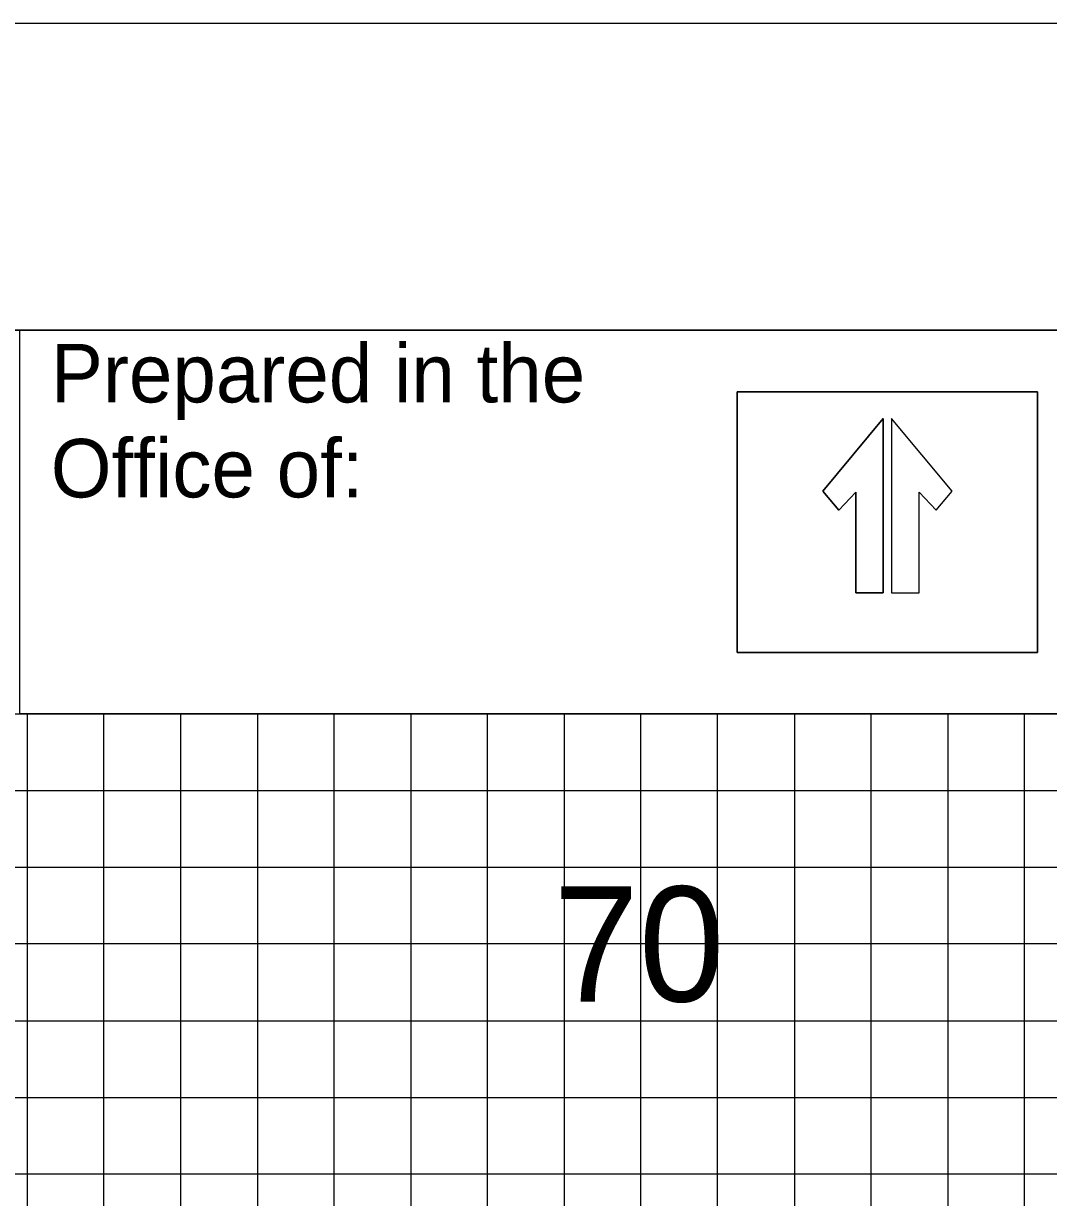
# Model space of a CAD drawing. Extents: x -13 to 323, y 655 to 874.
# Drawn here: x 221.95 to 235.31, y 858.69 to 874 of the extents above; entities that cross this region are included whole.
import ezdxf

# ---------------------------------------------------------------- set-up
doc = ezdxf.new("R2010")
doc.units = 0
for name, color, linetype in [('Exist Cross Section Cell', 7, 'Continuous'), ('Prop CMT Guardrail Widen Shoulder', 7, 'Continuous'), ('Prop CMT Pvmt Course 3', 7, 'Continuous'), ('Prop CMT Shld Paved Course 1', 7, 'Continuous'), ('Prop CMT Shld Paved Course 2', 7, 'Continuous'), ('Prop CMT Shld Paved Course 3', 7, 'Continuous'), ('Prop CMT Slope Grass', 7, 'Continuous'), ('Prop CMT Subgrade Earthwork', 7, 'Continuous'), ('Prop XS Earthwork Shape', 7, 'Continuous'), ('Scratch_Level_3', 7, 'Continuous')]:
    doc.layers.add(name, color=color, linetype=linetype)

msp = doc.modelspace()

# ---------------------------------------------------------------- linework, layer by layer
at = {"layer": 'Prop CMT Guardrail Widen Shoulder'}
for points in [[(235.168, 869.199), (231.253, 869.199), (231.253, 865.801), (235.168, 865.801), (235.168, 869.199)], [(233.158, 868.851), (233.158, 866.579), (232.8, 866.579), (232.8, 867.89), (232.578, 867.655), (232.37, 867.904), (233.158, 868.851)], [(232.37, 867.904), (232.578, 867.655), (232.8, 867.89), (232.8, 866.579), (233.158, 866.579), (233.158, 868.851), (232.37, 867.904)], [(233.268, 868.851), (233.268, 866.579), (233.626, 866.579), (233.626, 867.89), (233.847, 867.655), (234.056, 867.904), (233.268, 868.851)]]:
    msp.add_lwpolyline(points, dxfattribs=at)
for points in [[(231.253, 869.199), (235.168, 869.199), (235.168, 865.801), (231.253, 865.801)], [(233.268, 868.851), (233.268, 866.579), (233.626, 866.579), (233.626, 867.89), (233.847, 867.655), (234.056, 867.904)]]:
    msp.add_lwpolyline(points, close=True, dxfattribs=at)
at = {"layer": 'Prop CMT Pvmt Course 3'}
msp.add_lwpolyline([(-13.4, 655), (323.3, 655), (323.3, 874), (-13.4, 874)], close=True, dxfattribs=at)
at = {"layer": 'Prop CMT Shld Paved Course 1'}
msp.add_line((0, 864), (320, 864), dxfattribs=at)
for points in [[(0, 863), (270, 863), (320, 863)], [(320, 862), (0, 862)], [(0, 861), (320, 861)], [(320, 859), (0, 859)]]:
    msp.add_lwpolyline(points, dxfattribs=at)
at = {"layer": 'Prop CMT Shld Paved Course 2'}
msp.add_lwpolyline([(320, 870), (0, 870), (0, 660), (320, 660)], close=True, dxfattribs=at)
at = {"layer": 'Prop CMT Shld Paved Course 3'}
for points in [[(220, 660), (221, 660), (221, 870), (222, 870)], [(223, 870), (224, 870)], [(226, 870), (227, 870)], [(228, 870), (229, 870)], [(231, 870), (232, 870)], [(233, 870), (234, 870)], [(222, 865), (222, 660)], [(222, 660), (223, 660), (223, 865)], [(224, 865), (224, 660)], [(225, 660), (226, 660), (226, 865)], [(227, 865), (227, 660)], [(227, 660), (228, 660), (228, 865)], [(229, 865), (229, 660)], [(230, 660), (231, 660), (231, 865)], [(232, 865), (232, 660)], [(232, 660), (233, 660), (233, 865)], [(234, 865), (234, 660)]]:
    msp.add_lwpolyline(points, dxfattribs=at)
at = {"layer": 'Prop CMT Slope Grass'}
for points in [[(145, 660), (155, 660), (155, 870), (165, 870), (165, 660), (175, 660), (175, 870), (185, 870), (185, 660), (195, 660), (195, 870), (205, 870), (205, 660), (215, 660), (215, 870), (225, 870)], [(235, 870), (245, 870)], [(0, 865), (275, 865)], [(225, 865), (225, 660), (235, 660), (235, 865)]]:
    msp.add_lwpolyline(points, dxfattribs=at)
at = {"layer": 'Prop CMT Subgrade Earthwork'}
msp.add_lwpolyline([(-10.8, 659), (322.4, 659), (322.4, 870), (-10.8, 870)], close=True, dxfattribs=at)
at = {"layer": 'Prop XS Earthwork Shape'}
msp.add_lwpolyline([(221.902, 870), (260, 870), (260, 865), (221.902, 865)], close=True, dxfattribs=at)
at = {"layer": 'Scratch_Level_3'}
for p, q in [((230, 870), (220, 870)), ((230, 660), (230, 865))]:
    msp.add_line(p, q, dxfattribs=at)
msp.add_lwpolyline([(0, 860), (320, 860)], dxfattribs=at)

# ---------------------------------------------------------------- texts
at = {"layer": 'Exist Cross Section Cell'}
msp.add_text('70', height=1.5, dxfattribs=at).set_placement((228.858, 861.25))
at = {"layer": 'Prop CMT Guardrail Widen Shoulder'}
for s, height, p in [('Prepared in the ', 0.76195, (222.307, 869.06)), ('Office of:', 0.762, (222.307, 867.822))]:
    msp.add_text(s, height=height, rotation=360, dxfattribs=at).set_placement(p)

doc.saveas('drawing.dxf')
